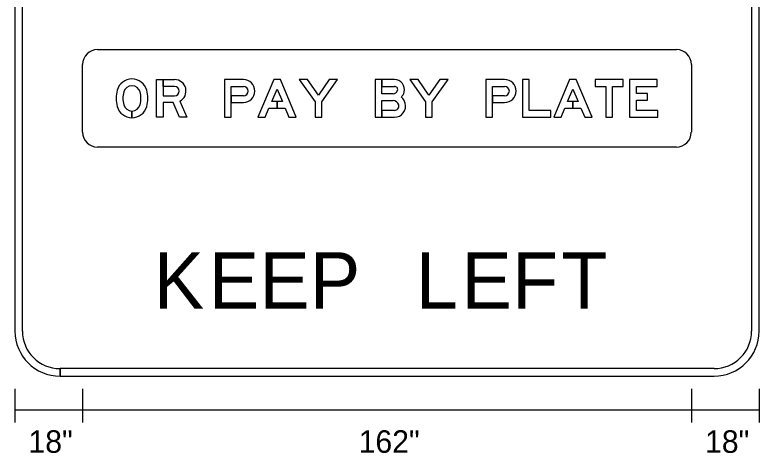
# Model space of a CAD drawing. Extents: x 10268312 to 10268472, y 2142583 to 2142688.
# Drawn here: x 10268355.48 to 10268380.23, y 2142658.34 to 2142672.94 of the extents above; entities that cross this region are included whole.
import ezdxf

# ---------------------------------------------------------------- set-up
doc = ezdxf.new("R2010")
doc.units = 0
for name, color, linetype in [('GSBWFill', 7, 'Continuous'), ('GSDims', 7, 'Continuous'), ('SignPanel', 7, 'Continuous')]:
    doc.layers.add(name, color=color, linetype=linetype)

msp = doc.modelspace()

# ---------------------------------------------------------------- linework, layer by layer
at = {"layer": 'GSBWFill'}
for p, q in [((10268355.48, 2142682.656), (10268355.48, 2142662.406)), ((10268355.73, 2142662.406), (10268355.73, 2142682.656)), ((10268379.98, 2142682.656), (10268379.98, 2142662.406)), ((10268380.23, 2142662.406), (10268380.23, 2142682.656)), ((10268358.232, 2142671.781), (10268377.477, 2142671.781)), ((10268357.732, 2142669.031), (10268357.732, 2142671.281)), ((10268377.977, 2142671.281), (10268377.977, 2142669.031)), ((10268377.477, 2142668.531), (10268358.232, 2142668.531)), ((10268356.98, 2142660.906), (10268356.98, 2142661.156)), ((10268378.73, 2142661.156), (10268356.982, 2142661.156)), ((10268356.982, 2142661.156), (10268356.982, 2142660.906)), ((10268356.982, 2142660.906), (10268378.73, 2142660.906))]:
    msp.add_line(p, q, dxfattribs=at)
for centre, radius, start, end in [((10268358.232, 2142671.281), 0.5, 90, 180), ((10268377.477, 2142671.281), 0.5, 0, 90), ((10268358.232, 2142669.031), 0.5, 180, 270), ((10268377.473, 2142669.031), 0.5, 270, 0), ((10268356.98, 2142662.406), 1.5, 180, 270), ((10268356.98, 2142662.406), 1.25, 180, 270), ((10268378.73, 2142662.406), 1.5, 270, 0), ((10268378.73, 2142662.406), 1.25, 270, 0)]:
    msp.add_arc(centre, radius, start, end, dxfattribs=at)
at = {"layer": 'GSDims'}
for p, q in [((10268355.48, 2142660.484), (10268355.48, 2142659.359)), ((10268357.73, 2142660.484), (10268357.73, 2142659.359)), ((10268377.98, 2142660.484), (10268377.98, 2142659.359)), ((10268380.23, 2142660.484), (10268380.23, 2142659.359)), ((10268355.48, 2142659.781), (10268357.73, 2142659.781)), ((10268357.73, 2142659.781), (10268377.98, 2142659.781)), ((10268377.98, 2142659.781), (10268380.23, 2142659.781))]:
    msp.add_line(p, q, dxfattribs=at)
at = {"layer": 'SignPanel'}
for p, q in [((10268362.673, 2142670.556), (10268363.08, 2142670.556)), ((10268371.361, 2142670.556), (10268371.767, 2142670.556)), ((10268359.373, 2142669.51), (10268359.373, 2142669.735)), ((10268359.373, 2142669.735), (10268359.373, 2142669.51))]:
    msp.add_line(p, q, dxfattribs=at)
for points in [[(10268360.968, 2142670.063), (10268361.198, 2142669.531), (10268360.953, 2142669.531), (10268360.742, 2142670.019), (10268360.411, 2142670.019), (10268360.411, 2142669.531), (10268360.186, 2142669.531), (10268360.186, 2142670.781), (10268360.411, 2142670.781), (10268360.411, 2142670.244), (10268360.79, 2142670.244)], [(10268360.411, 2142670.556), (10268360.411, 2142670.781), (10268360.79, 2142670.781)], [(10268363.08, 2142670.781), (10268362.448, 2142670.781), (10268362.448, 2142669.531), (10268362.673, 2142669.531), (10268362.673, 2142670.556)], [(10268368.056, 2142670.306), (10268367.686, 2142670.306), (10268367.686, 2142670.781), (10268367.461, 2142670.781), (10268367.461, 2142669.531), (10268367.686, 2142669.531)], [(10268368.105, 2142670.781), (10268367.686, 2142670.781), (10268367.686, 2142670.556), (10268368.105, 2142670.556)], [(10268371.767, 2142670.781), (10268371.136, 2142670.781), (10268371.136, 2142669.531), (10268371.361, 2142669.531), (10268371.361, 2142670.556)], [(10268360.79, 2142670.556), (10268360.411, 2142670.556)], [(10268363.08, 2142670.244), (10268362.673, 2142670.244), (10268362.673, 2142670.019), (10268363.08, 2142670.019)], [(10268367.686, 2142669.531), (10268367.686, 2142670.081), (10268368.056, 2142670.081)], [(10268371.767, 2142670.244), (10268371.361, 2142670.244), (10268371.361, 2142670.019), (10268371.767, 2142670.019)], [(10268368.105, 2142669.756), (10268367.686, 2142669.756), (10268367.686, 2142669.531), (10268368.105, 2142669.531)]]:
    msp.add_lwpolyline(points, dxfattribs=at)
for points in [[(10268364.374, 2142670.05), (10268364.198, 2142670.05), (10268364.198, 2142669.825), (10268364.468, 2142669.825), (10268364.592, 2142669.531), (10268364.836, 2142669.531), (10268364.311, 2142670.781), (10268364.086, 2142670.781), (10268363.561, 2142669.531), (10268363.805, 2142669.531), (10268363.928, 2142669.825), (10268364.198, 2142669.825), (10268364.198, 2142670.05), (10268364.023, 2142670.05), (10268364.198, 2142670.468)], [(10268365.686, 2142670.038), (10268366.211, 2142670.781), (10268365.935, 2142670.781), (10268365.573, 2142670.268), (10268365.211, 2142670.781), (10268364.936, 2142670.781), (10268365.461, 2142670.038), (10268365.461, 2142669.531), (10268365.686, 2142669.531)], [(10268369.361, 2142670.038), (10268369.886, 2142670.781), (10268369.61, 2142670.781), (10268369.248, 2142670.268), (10268368.886, 2142670.781), (10268368.611, 2142670.781), (10268369.136, 2142670.038), (10268369.136, 2142669.531), (10268369.361, 2142669.531)], [(10268373.298, 2142669.531), (10268373.298, 2142669.75), (10268372.586, 2142669.75), (10268372.586, 2142670.781), (10268372.361, 2142670.781), (10268372.361, 2142669.531)], [(10268374.211, 2142670.05), (10268374.036, 2142670.05), (10268374.036, 2142669.825), (10268374.306, 2142669.825), (10268374.429, 2142669.531), (10268374.673, 2142669.531), (10268374.148, 2142670.781), (10268373.923, 2142670.781), (10268373.398, 2142669.531), (10268373.642, 2142669.531), (10268373.766, 2142669.825), (10268374.036, 2142669.825), (10268374.036, 2142670.05), (10268373.86, 2142670.05), (10268374.036, 2142670.468)], [(10268374.773, 2142670.556), (10268375.13, 2142670.556), (10268375.13, 2142669.531), (10268375.355, 2142669.531), (10268375.355, 2142670.556), (10268375.711, 2142670.556), (10268375.711, 2142670.781), (10268374.773, 2142670.781)], [(10268376.861, 2142669.756), (10268376.148, 2142669.756), (10268376.148, 2142670.093), (10268376.517, 2142670.093), (10268376.517, 2142670.318), (10268376.148, 2142670.318), (10268376.148, 2142670.556), (10268376.842, 2142670.556), (10268376.842, 2142670.781), (10268375.923, 2142670.781), (10268375.923, 2142669.531), (10268376.861, 2142669.531)]]:
    msp.add_lwpolyline(points, close=True, dxfattribs=at)
for centre, radius, start, end in [((10268359.373, 2142670.297), 0.507, 14.9618, 165.0382), ((10268359.373, 2142670.297), 0.282, 14.9618, 165.0382), ((10268360.79, 2142670.4), 0.381, 297.837, 90), ((10268363.08, 2142670.4), 0.381, 270, 90), ((10268368.105, 2142670.45), 0.331, 345.5225, 90), ((10268371.767, 2142670.4), 0.381, 270, 90), ((10268359.898, 2142670.156), 1.05, 165.0382, 194.9618), ((10268359.898, 2142670.156), 0.825, 165.0382, 194.9618), ((10268358.848, 2142670.156), 0.825, 345.0382, 14.9618), ((10268358.848, 2142670.156), 1.05, 345.0382, 14.9618), ((10268360.79, 2142670.4), 0.156, 270, 90), ((10268363.08, 2142670.4), 0.156, 270, 90), ((10268368.056, 2142670.463), 0.156, 270, 345.5225), ((10268368.105, 2142670.45), 0.106, 345.5225, 90), ((10268368.056, 2142670.463), 0.381, 316.7114, 345.5225), ((10268371.767, 2142670.4), 0.156, 270, 90), ((10268368.056, 2142669.888), 0.194, 14.4775, 90), ((10268368.056, 2142669.888), 0.419, 14.4775, 48.4921), ((10268359.373, 2142670.016), 0.507, 194.9618, 270), ((10268359.373, 2142670.016), 0.282, 194.9618, 270), ((10268359.373, 2142670.016), 0.282, 270.0127, 345.0382), ((10268359.373, 2142670.016), 0.507, 270.0071, 345.0382), ((10268368.105, 2142669.9), 0.369, 270, 14.4775), ((10268368.105, 2142669.9), 0.144, 270, 14.4775)]:
    msp.add_arc(centre, radius, start, end, dxfattribs=at)

# ---------------------------------------------------------------- texts
at = {"layer": 'GSBWFill'}
for s, p in [('K', (10268360.097, 2142663.156)), ('E', (10268361.928, 2142663.156)), ('E', (10268363.61, 2142663.156)), ('P', (10268365.292, 2142663.156)), ('L', (10268368.817, 2142663.156)), ('E', (10268370.334, 2142663.156)), ('F', (10268372.016, 2142663.156)), ('T', (10268373.651, 2142663.156))]:
    msp.add_text(s, height=1.875, dxfattribs=at).set_placement(p)
at = {"layer": 'GSDims'}
for s, p in [('18"', (10268355.932, 2142658.353)), ('162"', (10268366.912, 2142658.353)), ('18"', (10268378.432, 2142658.353))]:
    msp.add_text(s, height=0.75, dxfattribs=at).set_placement(p)

doc.saveas('drawing.dxf')
